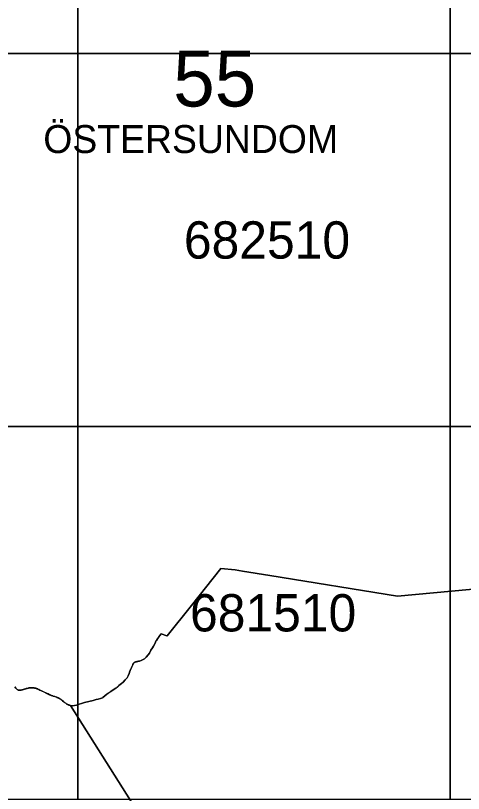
# Model space of a CAD drawing. Extents: x 25485000 to 25520000, y 6656775 to 6690000.
# Drawn here: x 25509833 to 25511036, y 6681015 to 6683102 of the extents above; entities that cross this region are included whole.
import ezdxf

# ---------------------------------------------------------------- set-up
doc = ezdxf.new("R2010")
doc.units = 0
doc.layers.add('Level 63', color=7, linetype='Continuous')

msp = doc.modelspace()

# ---------------------------------------------------------------- linework, layer by layer
at = {"layer": 'Level 63'}
for points in [[(25509000, 6683000), (25510000, 6683000), (25510000, 6684000), (25509000, 6684000)], [(25510000, 6683000), (25511000, 6683000), (25511000, 6684000), (25510000, 6684000)], [(25511000, 6683000), (25512000, 6683000), (25512000, 6684000), (25511000, 6684000)], [(25509000, 6682000), (25510000, 6682000), (25510000, 6683000), (25509000, 6683000)], [(25510000, 6682000), (25511000, 6682000), (25511000, 6683000), (25510000, 6683000)], [(25511000, 6682000), (25512000, 6682000), (25512000, 6683000), (25511000, 6683000)], [(25509000, 6681000), (25510000, 6681000), (25510000, 6682000), (25509000, 6682000)], [(25510000, 6681000), (25511000, 6681000), (25511000, 6682000), (25510000, 6682000)], [(25511000, 6681000), (25512000, 6681000), (25512000, 6682000), (25511000, 6682000)]]:
    msp.add_lwpolyline(points, close=True, dxfattribs=at)
for points in [[(25509831.3, 6681301.5), (25509833.7, 6681298.2), (25509835, 6681296.7), (25509836.3, 6681295.3), (25509837.9, 6681294), (25509839.7, 6681293), (25509840.5, 6681292.7), (25509842.5, 6681292.3), (25509844.5, 6681292.2), (25509846.5, 6681292.4), (25509848.5, 6681292.7), (25509850.4, 6681293.2), (25509852.3, 6681293.7), (25509854.3, 6681294.2), (25509854.8, 6681294.4), (25509855.6, 6681294.8), (25509856.4, 6681295), (25509857.2, 6681295.3), (25509859, 6681295.8), (25509860.9, 6681296.3), (25509864.5, 6681297.3), (25509866.9, 6681297.9), (25509867.5, 6681298), (25509868, 6681298.1), (25509868.4, 6681298.2), (25509868.9, 6681298.3), (25509869.6, 6681298.4), (25509870.3, 6681298.5), (25509870.8, 6681298.6), (25509871.6, 6681298.6), (25509872.3, 6681298.7), (25509872.8, 6681298.8), (25509873.6, 6681298.8), (25509874.3, 6681298.9), (25509874.8, 6681298.9), (25509875.4, 6681298.9), (25509876, 6681298.9), (25509876.4, 6681298.9), (25509877.1, 6681298.9), (25509877.9, 6681298.9), (25509878.4, 6681298.9), (25509879.1, 6681298.8), (25509879.9, 6681298.8), (25509880.4, 6681298.7), (25509881.1, 6681298.7), (25509881.8, 6681298.6), (25509882.3, 6681298.5), (25509883.1, 6681298.4), (25509883.8, 6681298.3), (25509884.3, 6681298.2), (25509885, 6681298), (25509885.8, 6681297.9), (25509886.3, 6681297.8), (25509887, 6681297.6), (25509887.7, 6681297.4), (25509888.2, 6681297.2), (25509888.9, 6681297), (25509889.6, 6681296.8), (25509890.1, 6681296.6), (25509890.8, 6681296.4), (25509891.5, 6681296.1), (25509892, 6681295.9), (25509892.7, 6681295.7), (25509892.9, 6681295.6), (25509893.2, 6681295.4), (25509893.4, 6681295.4), (25509896.1, 6681294.1), (25509898.8, 6681292.8), (25509902.6, 6681290.9), (25509902.8, 6681290.8), (25509903, 6681290.7), (25509909, 6681287.7), (25509915, 6681284.7), (25509919.1, 6681282.8), (25509924.6, 6681280.3), (25509925.6, 6681279.9), (25509926.7, 6681279.4), (25509928.8, 6681278.6), (25509930.2, 6681278.1), (25509932, 6681277.4), (25509932.9, 6681277.1), (25509933.8, 6681276.8), (25509938.5, 6681275.2), (25509943.3, 6681273.6), (25509943.8, 6681273.4), (25509944.3, 6681273.2), (25509945.4, 6681272.8), (25509946, 6681272.5), (25509947, 6681272.1), (25509947.6, 6681271.8), (25509948.3, 6681271.4), (25509948.8, 6681271.2), (25509949.4, 6681270.9), (25509950.1, 6681270.5), (25509950.5, 6681270.3), (25509951.2, 6681269.9), (25509951.8, 6681269.6), (25509952.3, 6681269.3), (25509952.5, 6681269.2), (25509952.7, 6681269), (25509952.9, 6681268.9), (25509953.5, 6681268.5), (25509954.1, 6681268.1), (25509954.5, 6681267.8), (25509955.1, 6681267.3), (25509955.7, 6681266.9), (25509956.1, 6681266.6), (25509957.9, 6681265.2), (25509959.6, 6681263.8), (25509963.1, 6681260.9), (25509965.4, 6681259), (25509966, 6681258.6), (25509966.6, 6681258.1), (25509967.8, 6681257.2), (25509968.7, 6681256.6), (25509969, 6681256.4), (25509969.3, 6681256.2), (25509969.9, 6681255.8), (25509970.3, 6681255.5), (25509970.8, 6681255.3), (25509971.3, 6681255), (25509971.6, 6681254.8), (25509972.1, 6681254.5), (25509972.6, 6681254.3), (25509973.1, 6681254), (25509973.4, 6681253.9), (25509973.8, 6681253.6), (25509974.3, 6681253.4), (25509974.7, 6681253.3), (25509975, 6681253.1), (25509975.7, 6681252.9), (25509976.3, 6681252.7), (25509976.7, 6681252.5), (25509976.9, 6681252.5), (25509978.8, 6681251.9), (25509980.7, 6681251.3), (25509986.4, 6681250.6), (25509997.1, 6681252.2), (25510003.8, 6681254.8), (25510010.5, 6681256.4), (25510018, 6681259), (25510042, 6681264.8), (25510049.2, 6681267.4), (25510055, 6681268.2), (25510061.6, 6681270.3), (25510066.6, 6681272.3), (25510067, 6681272.6), (25510067.4, 6681273), (25510073, 6681277.3), (25510078.5, 6681281.5), (25510081.2, 6681283.5), (25510084, 6681285.5), (25510085.8, 6681286.8), (25510088.3, 6681288.4), (25510088.6, 6681288.6), (25510088.8, 6681288.7), (25510095.5, 6681293.1), (25510102.2, 6681297.4), (25510102.9, 6681297.9), (25510103.6, 6681298.4), (25510104, 6681298.7), (25510104.6, 6681299.2), (25510105.4, 6681299.8), (25510106.6, 6681300.8), (25510107.7, 6681301.7), (25510108.5, 6681302.4), (25510108.8, 6681302.7), (25510109.1, 6681303), (25510109.4, 6681303.2), (25510110.1, 6681303.9), (25510110.8, 6681304.6), (25510117.6, 6681310.2), (25510121.7, 6681314.1), (25510127.5, 6681320.2), (25510132.5, 6681325.9), (25510135.2, 6681331.2), (25510138, 6681336.9), (25510140.4, 6681343.5), (25510140.6, 6681344.2), (25510140.9, 6681344.9), (25510141, 6681345.4), (25510141.2, 6681345.8), (25510141.5, 6681346.8), (25510141.6, 6681347), (25510141.7, 6681347.2), (25510141.7, 6681347.4), (25510141.8, 6681347.6), (25510142.5, 6681349.1), (25510143.2, 6681350.5), (25510144.7, 6681353.5), (25510145.7, 6681355.4), (25510146.2, 6681356.6), (25510146.3, 6681356.8), (25510146.4, 6681357.1), (25510147.1, 6681358.9), (25510147.8, 6681360.8), (25510148.1, 6681361.3), (25510148.3, 6681361.8), (25510148.4, 6681362.2), (25510148.6, 6681362.6), (25510148.8, 6681362.9), (25510148.9, 6681363.2), (25510149, 6681363.4), (25510149.2, 6681363.6), (25510149.4, 6681363.9), (25510149.7, 6681364.3), (25510149.9, 6681364.6), (25510150.1, 6681364.8), (25510150.2, 6681365), (25510150.4, 6681365.2), (25510150.7, 6681365.5), (25510150.8, 6681365.7), (25510151, 6681365.8), (25510151.2, 6681366), (25510151.4, 6681366.2), (25510151.5, 6681366.3), (25510151.7, 6681366.4), (25510152, 6681366.6), (25510152.1, 6681366.7), (25510152.3, 6681366.8), (25510152.6, 6681367), (25510153, 6681367.2), (25510153.2, 6681367.3), (25510153.5, 6681367.5), (25510153.7, 6681367.5), (25510153.9, 6681367.6), (25510154.1, 6681367.7), (25510154.6, 6681367.9), (25510155.2, 6681368.1), (25510155.5, 6681368.2), (25510156, 6681368.3), (25510156.7, 6681368.5), (25510157.5, 6681368.7), (25510157.9, 6681368.8), (25510158.7, 6681369), (25510159.4, 6681369.1), (25510159.9, 6681369.2), (25510160.8, 6681369.4), (25510161.7, 6681369.6), (25510163.7, 6681370), (25510165.6, 6681370.4), (25510170.5, 6681372.1), (25510179.5, 6681376.8), (25510183.5, 6681380.7), (25510188.9, 6681386.8), (25510192.6, 6681392.1), (25510196.6, 6681399.6), (25510201.2, 6681406.2), (25510203.9, 6681410.5), (25510207.1, 6681416.7), (25510208.5, 6681421.5), (25510210.9, 6681425.5), (25510211.1, 6681425.8), (25510211.2, 6681426), (25510214.3, 6681430), (25510217.2, 6681434), (25510217.6, 6681434.5), (25510218, 6681435.1), (25510220.9, 6681439.2), (25510223.8, 6681443.2), (25510239.6, 6681438.3), (25510240.1, 6681438.1), (25510305.2, 6681519.6), (25510384.4, 6681618.7), (25510384.6, 6681619), (25510422.9, 6681614.8), (25510442.8, 6681611.6), (25510515.6, 6681599.9), (25510858.2, 6681544.6), (25511003.9, 6681558.2), (25511254.8, 6681581.6)], [(25511254.8, 6681581.6), (25511003.9, 6681558.2), (25510858.2, 6681544.6), (25510515.6, 6681599.9), (25510442.8, 6681611.6), (25510422.9, 6681614.8), (25510384.6, 6681619), (25510384.4, 6681618.7), (25510305.2, 6681519.6), (25510240.1, 6681438.1), (25510239.6, 6681438.3), (25510223.8, 6681443.2), (25510220.9, 6681439.2), (25510218, 6681435.1), (25510217.6, 6681434.5), (25510217.2, 6681434), (25510214.3, 6681430), (25510211.2, 6681426), (25510211.1, 6681425.8), (25510210.9, 6681425.5), (25510208.5, 6681421.5), (25510207.1, 6681416.7), (25510203.9, 6681410.5), (25510201.2, 6681406.2), (25510196.6, 6681399.6), (25510192.6, 6681392.1), (25510188.9, 6681386.8), (25510183.5, 6681380.7), (25510179.5, 6681376.8), (25510170.5, 6681372.1), (25510165.6, 6681370.4), (25510163.7, 6681370), (25510161.7, 6681369.6), (25510160.8, 6681369.4), (25510159.9, 6681369.2), (25510159.4, 6681369.1), (25510158.9, 6681369), (25510157.9, 6681368.8), (25510157.5, 6681368.7), (25510157, 6681368.6), (25510156, 6681368.3), (25510155.7, 6681368.2), (25510155.5, 6681368.2), (25510154.9, 6681368), (25510154.6, 6681367.9), (25510154.1, 6681367.7), (25510153.8, 6681367.6), (25510153.5, 6681367.5), (25510153.3, 6681367.4), (25510153.1, 6681367.3), (25510152.7, 6681367.1), (25510152.3, 6681366.8), (25510152.1, 6681366.7), (25510151.9, 6681366.5), (25510151.7, 6681366.4), (25510151.5, 6681366.3), (25510151.3, 6681366.1), (25510151.1, 6681366), (25510151, 6681365.8), (25510150.7, 6681365.6), (25510150.5, 6681365.3), (25510150.3, 6681365.1), (25510150.1, 6681364.9), (25510150, 6681364.7), (25510149.8, 6681364.5), (25510149.7, 6681364.3), (25510149.4, 6681364), (25510149.2, 6681363.6), (25510149.1, 6681363.4), (25510148.9, 6681363), (25510148.8, 6681362.8), (25510148.6, 6681362.6), (25510148.4, 6681362.1), (25510148.2, 6681361.6), (25510148, 6681361.2), (25510147.8, 6681360.8), (25510147.1, 6681358.9), (25510146.4, 6681357.1), (25510146.3, 6681356.8), (25510146.2, 6681356.6), (25510145.5, 6681355.1), (25510144.8, 6681353.6), (25510143.3, 6681350.7), (25510142.3, 6681348.7), (25510141.8, 6681347.6), (25510141.7, 6681347.4), (25510141.6, 6681347.1), (25510141.6, 6681347), (25510141.5, 6681346.8), (25510141.2, 6681346.1), (25510141, 6681345.4), (25510140.9, 6681344.9), (25510140.6, 6681344.2), (25510140.4, 6681343.5), (25510138, 6681336.9), (25510135.2, 6681331.2), (25510132.5, 6681325.9), (25510127.5, 6681320.2), (25510121.7, 6681314.1), (25510117.6, 6681310.2), (25510110.8, 6681304.6), (25510110.1, 6681303.9), (25510109.4, 6681303.2), (25510109.1, 6681303), (25510108.9, 6681302.8), (25510108.5, 6681302.4), (25510107.9, 6681301.9), (25510107.3, 6681301.4), (25510106.2, 6681300.5), (25510105.4, 6681299.8), (25510104.6, 6681299.2), (25510103.8, 6681298.6), (25510103.3, 6681298.2), (25510102.6, 6681297.7), (25510102.2, 6681297.4), (25510095.5, 6681293.1), (25510088.8, 6681288.7), (25510088.6, 6681288.6), (25510088.3, 6681288.4), (25510085.5, 6681286.5), (25510082.8, 6681284.6), (25510080.9, 6681283.3), (25510078.5, 6681281.5), (25510073, 6681277.3), (25510067.4, 6681273), (25510067, 6681272.6), (25510066.6, 6681272.3), (25510061.6, 6681270.3), (25510055, 6681268.2), (25510049.2, 6681267.4), (25510042, 6681264.8), (25510018, 6681259), (25510010.5, 6681256.4), (25510003.8, 6681254.8), (25509997.1, 6681252.2), (25509986.4, 6681250.6), (25509980.7, 6681251.3), (25510431.9, 6680537.6)], [(25510431.9, 6680537.6), (25509980.7, 6681251.3), (25509978.8, 6681251.9), (25509976.9, 6681252.5), (25509976.7, 6681252.5), (25509976.4, 6681252.6), (25509976, 6681252.8), (25509975, 6681253.1), (25509974.8, 6681253.2), (25509974.6, 6681253.3), (25509974.1, 6681253.5), (25509973.8, 6681253.6), (25509973.3, 6681253.9), (25509972.8, 6681254.1), (25509972.5, 6681254.3), (25509972.1, 6681254.5), (25509971.6, 6681254.8), (25509971.1, 6681255.1), (25509970.8, 6681255.3), (25509970.3, 6681255.5), (25509969.7, 6681255.9), (25509969.1, 6681256.4), (25509968.7, 6681256.6), (25509967.4, 6681257.5), (25509966.2, 6681258.4), (25509965.4, 6681259), (25509963.7, 6681260.4), (25509961.9, 6681261.8), (25509958.5, 6681264.7), (25509956.1, 6681266.6), (25509955.5, 6681267), (25509954.9, 6681267.5), (25509954.5, 6681267.8), (25509953.9, 6681268.2), (25509953.3, 6681268.6), (25509952.9, 6681268.9), (25509952.7, 6681269.1), (25509952.4, 6681269.2), (25509952.3, 6681269.3), (25509951.6, 6681269.7), (25509951, 6681270.1), (25509950.5, 6681270.3), (25509949.9, 6681270.7), (25509949.2, 6681271), (25509948.8, 6681271.2), (25509948.1, 6681271.6), (25509947.4, 6681271.9), (25509947, 6681272.1), (25509946.1, 6681272.5), (25509945.2, 6681272.9), (25509944.5, 6681273.1), (25509943.7, 6681273.4), (25509943.3, 6681273.6), (25509938.5, 6681275.2), (25509933.8, 6681276.8), (25509932.9, 6681277.1), (25509932, 6681277.4), (25509929.9, 6681278.2), (25509927.8, 6681279), (25509926.4, 6681279.5), (25509924.6, 6681280.3), (25509920.5, 6681282.2), (25509916.4, 6681284.1), (25509908.3, 6681288), (25509903, 6681290.7), (25509902.8, 6681290.8), (25509902.6, 6681290.9), (25509898.8, 6681292.8), (25509896.1, 6681294.1), (25509893.4, 6681295.4), (25509893.2, 6681295.4), (25509893, 6681295.5), (25509892.7, 6681295.7), (25509892, 6681295.9), (25509891.3, 6681296.2), (25509890.6, 6681296.5), (25509890.1, 6681296.6), (25509889.4, 6681296.9), (25509888.7, 6681297.1), (25509888.2, 6681297.2), (25509887.5, 6681297.4), (25509886.8, 6681297.6), (25509886.3, 6681297.8), (25509885.5, 6681297.9), (25509884.8, 6681298.1), (25509884.3, 6681298.2), (25509883.6, 6681298.3), (25509882.8, 6681298.4), (25509882.3, 6681298.5), (25509881.6, 6681298.6), (25509880.9, 6681298.7), (25509880.4, 6681298.7), (25509879.6, 6681298.8), (25509878.9, 6681298.9), (25509878.4, 6681298.9), (25509877.6, 6681298.9), (25509876.9, 6681298.9), (25509876.4, 6681298.9), (25509875.8, 6681298.9), (25509875.2, 6681298.9), (25509874.8, 6681298.9), (25509874.1, 6681298.9), (25509873.3, 6681298.8), (25509872.8, 6681298.8), (25509872.1, 6681298.7), (25509871.3, 6681298.6), (25509870.8, 6681298.6), (25509870.1, 6681298.5), (25509869.4, 6681298.3), (25509868.9, 6681298.3), (25509868.3, 6681298.2), (25509867.8, 6681298.1), (25509867.4, 6681298), (25509866.9, 6681297.9), (25509864.2, 6681297.2), (25509861.5, 6681296.5), (25509859.6, 6681296), (25509857.2, 6681295.3), (25509856.4, 6681295), (25509855.6, 6681294.8), (25509854.8, 6681294.4), (25509854.3, 6681294.2), (25509852.3, 6681293.7), (25509850.4, 6681293.2), (25509848.5, 6681292.7), (25509846.5, 6681292.4), (25509844.5, 6681292.2), (25509842.5, 6681292.3), (25509840.5, 6681292.7), (25509839.7, 6681293), (25509837.9, 6681294), (25509836.3, 6681295.3), (25509835, 6681296.7), (25509833.7, 6681298.2), (25509831.3, 6681301.5)]]:
    msp.add_lwpolyline(points, dxfattribs=at)

# ---------------------------------------------------------------- texts
for s, height, p in [('55', 150, (25510256.3, 6682858.1)), ('ÖSTERSUNDOM', 75, (25509907.7, 6682733.2)), ('682510', 100, (25510285.1, 6682450)), ('681510', 100, (25510301.6, 6681450))]:
    msp.add_text(s, height=height, dxfattribs=at).set_placement(p)

doc.saveas('drawing.dxf')
